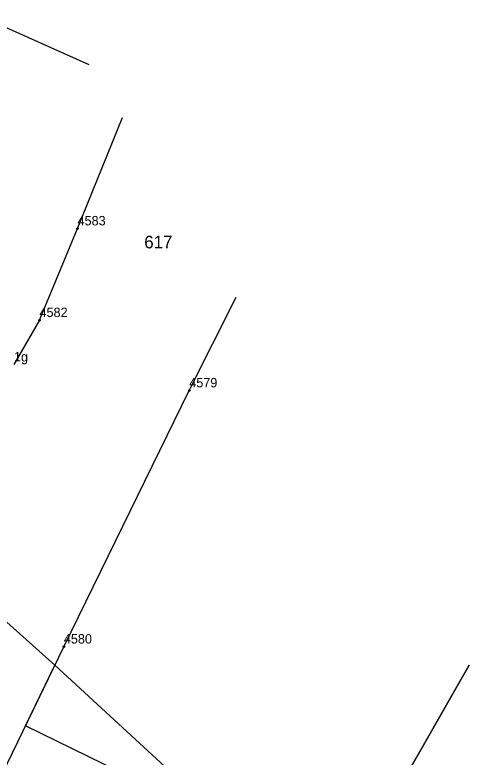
# Model space of a CAD drawing. Extents: x 7465393 to 7466459, y 5491258 to 5492404.
# Drawn here: x 7465961.5 to 7466015.6, y 5491723 to 5491811.4 of the extents above; entities that cross this region are included whole.
import ezdxf

# ---------------------------------------------------------------- set-up
doc = ezdxf.new("R2010")
doc.units = 0
for name, color, linetype in [('203-punkt graniczny', 7, 'Continuous'), ('203-punkt graniczny-Atr103', 7, 'Continuous'), ('211-numer działki ewidencyjnej', 7, 'Continuous'), ('217-kontur klasyfikacyjny', 7, 'Continuous'), ('218-kontur użytku gruntowego', 7, 'Continuous'), ('219-działka ewidencyjna', 7, 'Continuous')]:
    doc.layers.add(name, color=color, linetype=linetype)

# ---------------------------------------------------------------- blocks, each defined once
blk = doc.blocks.new('203')
blk.add_circle((0, 0), 0.09)

msp = doc.modelspace()

# ---------------------------------------------------------------- linework, layer by layer
at = {"layer": '217-kontur klasyfikacyjny'}
for points in [[(7465966.25, 5491733.95), (7465949.48, 5491748.9)], [(7465986.92, 5491714.85), (7465966.25, 5491733.95)]]:
    msp.add_lwpolyline(points, dxfattribs=at)
at = {"layer": '218-kontur użytku gruntowego'}
for points in [[(7465966.25, 5491733.95), (7465949.48, 5491748.9)], [(7465962.73, 5491726.69), (7465966.25, 5491733.95)], [(7466015.594, 5491733.941), (7466007.15, 5491719.1)], [(7465986.92, 5491714.85), (7465962.73, 5491726.69)]]:
    msp.add_lwpolyline(points, dxfattribs=at)
at = {"layer": '219-działka ewidencyjna'}
for points in [[(7465957.03, 5491811.41), (7465970.292, 5491805.498)], [(7465968.94, 5491785.95), (7465974.294, 5491799.177)], [(7465964.41, 5491775.03), (7465968.94, 5491785.95)], [(7465982.25, 5491766.65), (7465987.841, 5491777.778)], [(7465964.41, 5491775.03), (7465961.37, 5491769.74)], [(7465967.31, 5491736.13), (7465982.25, 5491766.65)], [(7465952.03, 5491704.63), (7465967.31, 5491736.13)], [(7466007.15, 5491719.1), (7466015.594, 5491733.941)]]:
    msp.add_lwpolyline(points, dxfattribs=at)

# ---------------------------------------------------------------- block references
at = {"layer": '203-punkt graniczny'}
for p in [(7465968.94, 5491785.95), (7465964.41, 5491775.03), (7465982.25, 5491766.65), (7465967.31, 5491736.13)]:
    msp.add_blockref('203', p, dxfattribs=at)

# ---------------------------------------------------------------- texts
at = {"layer": '203-punkt graniczny-Atr103'}
for s, p in [('4583', (7465968.94, 5491786.325)), ('4582', (7465964.41, 5491775.405)), ('1g', (7465961.37, 5491770.115)), ('4579', (7465982.25, 5491767.025)), ('4580', (7465967.31, 5491736.505))]:
    msp.add_text(s, height=1.125, dxfattribs=at).set_placement(p)
at = {"layer": '211-numer działki ewidencyjnej'}
msp.add_text('617', height=1.5, dxfattribs=at).set_placement((7465976.89, 5491783.59))

doc.saveas('drawing.dxf')
